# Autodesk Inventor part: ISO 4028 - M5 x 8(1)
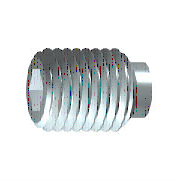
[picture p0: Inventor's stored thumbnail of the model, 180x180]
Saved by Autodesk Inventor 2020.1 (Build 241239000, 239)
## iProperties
Created: 2019-01
Part Number: ISO 4028 - M5 x 8(1)
Material: Edelstahl, 440C
Description: Innensechskant-Gewindestifte mit Zapfen
Document SubType Name: Modeling
Standard: ISO 4028
Designer: lutzd
Standard Revision: Third edition 2003-12-01
Standards Organization: ISO
Language: de-DE
Size Designation: M5 x 8
Categories: <MemberInstance><Categories><Category DisplayName="Verbindungselemente" InternalName="e4da775c-781d-43d5-af7c-5136215cf5a6" Mnemonic="FSTN"><Category DisplayNam
Mass: 0.839286 g
Surface Area: 1.68144 cm^2
Volume: 0.108295 cm^3
Density: 7.75 g/cm^3
Appearance: Halbpoliert
IsCustomPart: 0
Author: lutzd
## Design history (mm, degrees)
sketch "Skizze1"
  geometry: L1 (0, 0)-(4.167, 0); L2 (8, 1.443)-(8, 2.5); L3 (8, 2.5)-(2.5, 2.5); L4 (8, 1.443)-(5, 1.443); L5 (5, 1.443)-(4.167, 0); L6 (0, -0.5)-(0, 3) reference; L7 (0, 1.75)-(0, 0); L8 (0, 1.75)-(2.5, 1.75); L9 (2.5, 1.75)-(2.5, 2.5)
  constraints: 17 end point, 3 parallel, 3 perpendicular, 1 collinear, 1 point on line
  dimensions: "d0" = 3 distance of L2.start L4.end (= INTI); "d1" = 60 deg angle of L5 L1; "d2" = 5 diameter of L3 L1 (= NND); "d3" = 2.88675 diameter of L4 L1 (= 1.1547 x SW); "d5" = 8 distance from line of L2 L7.start (= NLG); "d7" = 3.5 diameter of L7.start L1 (= SPD); "d14" = 2.5 distance of L7.start L8.end (= ZLG)
revolve "Körper" sketch "Skizze1" stored, may be unused: angle "d6" = 90 deg
sketch "Skizze2"
  geometry: L1 (-0.722, 1.25)-(0.722, 1.25); L2 (0.722, 1.25)-(1.443, 0); L3 (1.443, 0)-(0.722, -1.25); L4 (0.722, -1.25)-(-0.722, -1.25); L5 (-0.722, -1.25)-(-1.443, 0); L6 (-1.443, 0)-(-0.722, 1.25); A1 r 1.443 centre (0, 0) between (-0.722, 1.25) and (0.722, 1.25) reference; 2 further points
  constraints: 12 end point, 2 point on circle, 1 coincident, 1 horizontal, 11 other
extrude "Loch" join sketch "Skizze2" taper "d10" = 0 deg; stored distance "d21" = 10
workaxis "Work Axis1"
workplane "Work Plane1"
body "Solid1"
chamfer "Fase1" distance "d8" = 0.49076 (computed from NND, GD1, FAWI); stored, may be unused: angle "d9" = 45 deg (= FAWI), second distance "d30" = 0.49076 (computed from NND, GD1, FAWI)
feature "Gewinde" dims "d12" = 5.5 (= NLG - ZLG), "d13" = 0
chamfer "Fase2" distance "d15" = 0.75 (computed from NND, SPD, FAWI1); stored, may be unused: angle "d16" = 45 deg (= FAWI1), second distance "d31" = 0.75 (computed from NND, SPD, FAWI1)
other parameters: "NND" = 5 [user parameter; used in 5 equation terms], "NLG" = 8 [user parameter; used in 2 equation terms], "INTI" = 3 [user parameter; used in 1 equation term], "FAWI" = 45 deg [user parameter; used in 3 equation terms], "SW" = 2.5 [user parameter; used in 2 equation terms], "GD1" = 4.01848 (= THREADDIA - 1.2269 x PTC) [user parameter; used in 2 equation terms], "d4" = 0, "FAWI1" = 45 deg [user parameter; used in 3 equation terms], "SPD" = 3.5 [user parameter; used in 3 equation terms], "ZLG" = 2.5 [user parameter; used in 2 equation terms], "d32" = 0, "d33" = 0, "GUL" = 0.49076 (= 0.61345 x PTC) [user parameter], "TPU" = 12.5 (computed from PTC) [user parameter], "TOA" = 30 deg [user parameter], "THREADDIA" = 5 [user parameter; used in 1 equation term], "PTC" = 0.8 [user parameter; used in 4 equation terms], "GAL" = 0.49076 (= 0.61345 x PTC) [user parameter], "E0" = 2.8875 (= 1.155 x SW) [user parameter]
